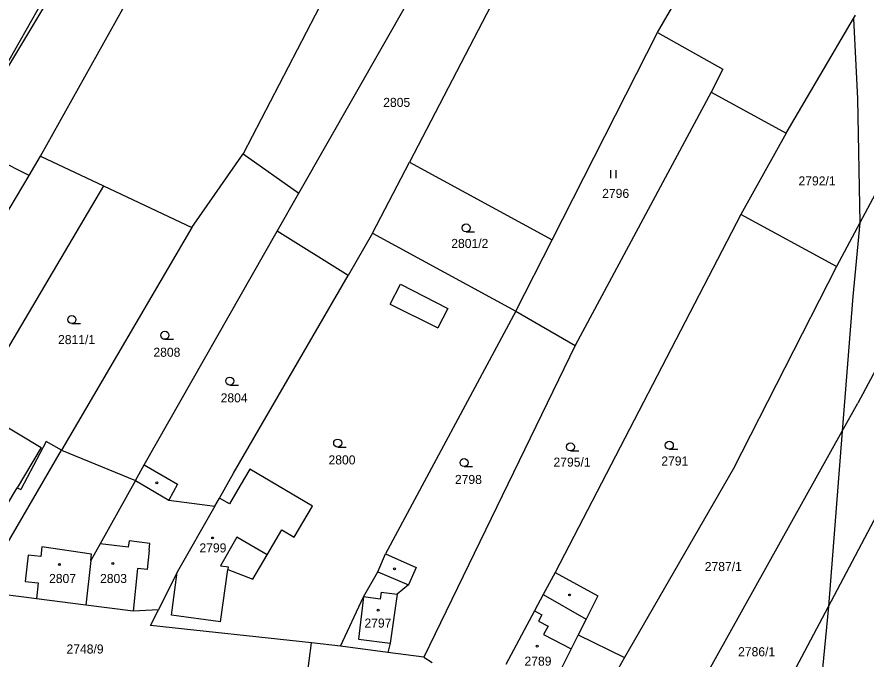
# Model space of a CAD drawing. Extents: x -755819 to -753140, y -1169796 to -1166000.
# Drawn here: x -753865.3 to -753706, y -1169016.5 to -1168896.1 of the extents above; entities that cross this region are included whole.
import ezdxf

# ---------------------------------------------------------------- set-up
doc = ezdxf.new("R2010")
doc.units = 0
for name, color, linetype in [('Vrstva 1', 7, 'Continuous'), ('Vrstva 18', 7, 'Continuous'), ('Vrstva 19', 7, 'Continuous'), ('Vrstva 25', 7, 'Continuous'), ('Vrstva 4', 7, 'Continuous'), ('Vrstva 6', 7, 'Continuous')]:
    doc.layers.add(name, color=color, linetype=linetype)

msp = doc.modelspace()

# ---------------------------------------------------------------- linework, layer by layer
at = {"layer": 'Vrstva 1'}
for p, q in [((-753776.72, -1168832.59), (-753822.86, -1168921.71)), ((-753860.84, -1168922.15), (-753819.74, -1168848.57)), ((-753745.13, -1168898.97), (-753723.98, -1168862.19)), ((-753765.92, -1168873.82), (-753791.66, -1168923.33)), ((-753812.4, -1168929.1), (-753791.66, -1168892.68)), ((-753859.75, -1168893.38), (-753875.49, -1168919.49)), ((-753708.4, -1168896.39), (-753708.03, -1168895.76)), ((-753721.02, -1168917.88), (-753708.4, -1168896.39)), ((-753708.4, -1168896.39), (-753707.61, -1168911.45)), ((-753764.9, -1168937.85), (-753745.13, -1168898.97)), ((-753745.13, -1168898.97), (-753732.89, -1168905.86)), ((-753732.89, -1168905.86), (-753735.09, -1168910.19)), ((-753735.09, -1168910.19), (-753760.61, -1168957.65)), ((-753735.09, -1168910.19), (-753721.02, -1168917.88)), ((-753707.61, -1168911.45), (-753707.21, -1168934.67)), ((-753721.02, -1168917.88), (-753729.53, -1168933.1)), ((-753863, -1168925.78), (-753875.49, -1168919.49)), ((-753863, -1168925.78), (-753860.84, -1168922.15)), ((-753860.84, -1168922.15), (-753849.08, -1168927.71)), ((-753832.5, -1168935.54), (-753822.86, -1168921.71)), ((-753822.86, -1168921.71), (-753812.4, -1168929.1)), ((-753798.58, -1168936.64), (-753791.66, -1168923.33)), ((-753791.66, -1168923.33), (-753764.9, -1168937.85)), ((-753684.02, -1168924.11), (-753707.57, -1168968.51)), ((-753908.16, -1169001.74), (-753863, -1168925.78)), ((-753849.08, -1168927.71), (-753893.24, -1169002.57)), ((-753849.08, -1168927.71), (-753832.5, -1168935.54)), ((-753702.9, -1168926.61), (-753707.21, -1168934.67)), ((-753816.46, -1168936.24), (-753812.4, -1168929.1)), ((-753713.1, -1169006.62), (-753671.62, -1168928.26)), ((-753729.53, -1168933.1), (-753764.36, -1169000.22)), ((-753711.59, -1168942.84), (-753729.53, -1168933.1)), ((-753832.5, -1168935.54), (-753856.95, -1168977.33)), ((-753707.21, -1168934.67), (-753711.59, -1168942.84)), ((-753707.21, -1168934.67), (-753708.52, -1168948.5)), ((-753841.4, -1168980.06), (-753816.46, -1168936.24)), ((-753803.16, -1168944.53), (-753816.46, -1168936.24)), ((-753798.58, -1168936.64), (-753803.16, -1168944.53)), ((-753798.58, -1168936.64), (-753771.7, -1168951.23)), ((-753771.7, -1168951.23), (-753764.9, -1168937.85)), ((-753711.59, -1168942.84), (-753730.93, -1168980.89)), ((-753824.65, -1168981.62), (-753803.16, -1168944.53)), ((-753708.52, -1168948.5), (-753710.51, -1168973.77)), ((-753771.7, -1168951.23), (-753796.14, -1168996.72)), ((-753771.7, -1168951.23), (-753760.61, -1168957.65)), ((-753760.61, -1168957.65), (-753788.98, -1169016.12)), ((-753710.51, -1168973.77), (-753707.57, -1168968.51)), ((-753870.59, -1168970.91), (-753860.74, -1168976.78)), ((-753743.31, -1169032.56), (-753710.51, -1168973.77)), ((-753710.51, -1168973.77), (-753713.1, -1169006.62)), ((-753859.78, -1168975.69), (-753864.57, -1168984.66)), ((-753856.95, -1168977.33), (-753859.78, -1168975.69)), ((-753867.49, -1168995.5), (-753856.95, -1168977.33)), ((-753860.74, -1168976.78), (-753865.24, -1168984.37)), ((-753856.95, -1168977.33), (-753843.08, -1168983.01)), ((-753843.08, -1168983.01), (-753841.4, -1168980.06)), ((-753841.4, -1168980.06), (-753835.18, -1168983.66)), ((-753827.3, -1168986.28), (-753824.65, -1168981.62)), ((-753821.62, -1168980.87), (-753823.43, -1168983.94)), ((-753809.86, -1168987.78), (-753821.62, -1168980.87)), ((-753730.93, -1168980.89), (-753751.33, -1169016.18)), ((-753843.08, -1168983.01), (-753849.68, -1168994.84)), ((-753835.18, -1168983.66), (-753836.78, -1168986.68)), ((-753865.24, -1168984.37), (-753864.57, -1168984.66)), ((-753823.43, -1168983.94), (-753825.4, -1168987.38)), ((-753836.78, -1168986.68), (-753828.16, -1168987.79)), ((-753828.16, -1168987.79), (-753827.3, -1168986.28)), ((-753825.4, -1168987.38), (-753827.3, -1168986.28)), ((-753828.16, -1168987.79), (-753835.24, -1169000.21)), ((-753813.3, -1168993.62), (-753809.86, -1168987.78)), ((-753818.34, -1168996.91), (-753815.63, -1168992.25)), ((-753815.63, -1168992.25), (-753813.3, -1168993.62)), ((-753849.68, -1168994.84), (-753851.42, -1168997.97)), ((-753851.42, -1168997.97), (-753852.36, -1169006.37)), ((-753821.05, -1169001.52), (-753818.34, -1168996.91)), ((-753797.6, -1169000.1), (-753796.14, -1168996.72)), ((-753796.14, -1168996.72), (-753790.41, -1168999.28)), ((-753827.1, -1169009.48), (-753825.75, -1168999.67)), ((-753825.75, -1168999.67), (-753821.05, -1169001.52)), ((-753790.41, -1168999.28), (-753791.87, -1169002.56)), ((-753835.24, -1169000.21), (-753838.76, -1169007.23)), ((-753836.28, -1169008.26), (-753835.24, -1169000.21)), ((-753800.29, -1169004.83), (-753797.6, -1169000.1)), ((-753764.36, -1169000.22), (-753766.57, -1169004.35)), ((-753764.36, -1169000.22), (-753756.31, -1169004.64)), ((-753791.87, -1169002.56), (-753793.98, -1169004.32)), ((-753864.02, -1169004.86), (-753872.23, -1169003.8)), ((-753793.98, -1169004.32), (-753795.28, -1169013.5)), ((-753766.57, -1169004.35), (-753768.22, -1169007.42)), ((-753861.64, -1169005.17), (-753864.02, -1169004.86)), ((-753852.36, -1169006.37), (-753861.64, -1169005.17)), ((-753804.59, -1169014.03), (-753800.29, -1169004.83)), ((-753756.31, -1169004.64), (-753758.51, -1169008.97)), ((-753843.51, -1169007.48), (-753852.36, -1169006.37)), ((-753838.76, -1169007.23), (-753843.51, -1169007.48)), ((-753840.24, -1169010.18), (-753838.76, -1169007.23)), ((-753768.22, -1169007.42), (-753773.61, -1169017.48)), ((-753732.98, -1169044.16), (-753713.1, -1169006.62)), ((-753713.1, -1169006.62), (-753717.26, -1169050.5)), ((-753827.1, -1169009.48), (-753836.28, -1169008.26)), ((-753758.51, -1169008.97), (-753760, -1169011.91)), ((-753810.05, -1169013.44), (-753840.24, -1169010.18)), ((-753760, -1169011.91), (-753761.35, -1169014.59)), ((-753760, -1169011.91), (-753751.33, -1169016.18)), ((-753811.64, -1169025.68), (-753810.05, -1169013.44)), ((-753804.59, -1169014.03), (-753810.05, -1169013.44)), ((-753795.28, -1169013.5), (-753795.7, -1169015.22)), ((-753795.7, -1169015.22), (-753804.59, -1169014.03)), ((-753788.98, -1169016.12), (-753795.7, -1169015.22)), ((-753761.35, -1169014.59), (-753764.74, -1169021.36)), ((-753788.98, -1169016.12), (-753787.44, -1169017.11)), ((-753751.33, -1169016.18), (-753758.36, -1169028.42))]:
    msp.add_line(p, q, dxfattribs=at)
at = {"layer": 'Vrstva 25'}
for p, q in [((-753753.87, -1168926.33), (-753753.87, -1168924.83)), ((-753752.87, -1168926.33), (-753752.87, -1168924.83)), ((-753781.04, -1168936.37), (-753779.44, -1168936.37)), ((-753854.99, -1168953.57), (-753853.39, -1168953.57)), ((-753837.54, -1168956.52), (-753835.94, -1168956.52)), ((-753825.36, -1168965.09), (-753823.76, -1168965.09)), ((-753805.13, -1168976.72), (-753803.53, -1168976.72)), ((-753742.93, -1168977.13), (-753741.33, -1168977.13)), ((-753761.47, -1168977.44), (-753759.87, -1168977.44)), ((-753781.43, -1168980.39), (-753779.83, -1168980.39))]:
    msp.add_line(p, q, dxfattribs=at)
for centre, radius in [((-753781.04, -1168935.62), 0.75), ((-753854.99, -1168952.82), 0.75), ((-753837.54, -1168955.77), 0.75), ((-753825.36, -1168964.34), 0.75), ((-753805.13, -1168975.97), 0.75), ((-753742.93, -1168976.38), 0.75), ((-753761.47, -1168976.69), 0.75), ((-753781.43, -1168979.64), 0.75), ((-753839.06, -1168983.45), 0.175), ((-753828.58, -1168993.77), 0.175), ((-753857.33, -1168998.75), 0.175), ((-753847.32, -1168998.54), 0.175), ((-753794.47, -1168999.56), 0.175), ((-753761.63, -1169004.46), 0.175), ((-753797.52, -1169007.31), 0.175), ((-753767.72, -1169014.05), 0.175)]:
    msp.add_circle(centre, radius, dxfattribs=at)
at = {"layer": 'Vrstva 4'}
for p, q in [((-753795.3, -1168949.92), (-753793.35, -1168946.15)), ((-753793.35, -1168946.15), (-753784.49, -1168950.71)), ((-753795.3, -1168949.92), (-753786.37, -1168954.36)), ((-753784.49, -1168950.71), (-753786.37, -1168954.36)), ((-753843.08, -1168983.01), (-753836.78, -1168986.68)), ((-753867.34, -1168987.91), (-753865.24, -1168984.37)), ((-753844.42, -1168995.52), (-753849.68, -1168994.84)), ((-753844.26, -1168994.32), (-753844.42, -1168995.52)), ((-753840.36, -1168994.82), (-753844.26, -1168994.32)), ((-753840.51, -1168996.02), (-753840.36, -1168994.82)), ((-753824.02, -1168993.63), (-753827.13, -1168998.98)), ((-753818.34, -1168996.91), (-753824.02, -1168993.63)), ((-753860.59, -1168995.42), (-753860.82, -1168997.25)), ((-753851.29, -1168996.82), (-753860.59, -1168995.42)), ((-753840.8, -1168999.7), (-753840.41, -1168996.03)), ((-753840.41, -1168996.03), (-753840.51, -1168996.02)), ((-753863.21, -1168997), (-753863.72, -1169001.96)), ((-753860.82, -1168997.25), (-753863.21, -1168997)), ((-753851.42, -1168997.97), (-753851.29, -1168996.82)), ((-753842.66, -1168999.51), (-753843.51, -1169007.48)), ((-753840.8, -1168999.7), (-753842.66, -1168999.51)), ((-753827.13, -1168998.98), (-753826.05, -1168999.11)), ((-753826.05, -1168999.11), (-753825.68, -1168999.17)), ((-753825.68, -1168999.17), (-753825.75, -1168999.67)), ((-753797.6, -1169000.1), (-753791.87, -1169002.56)), ((-753863.72, -1169001.96), (-753861.33, -1169002.2)), ((-753861.33, -1169002.2), (-753861.64, -1169005.17)), ((-753796.96, -1169003.91), (-753797.14, -1169005.26)), ((-753796.96, -1169003.91), (-753793.98, -1169004.32)), ((-753766.57, -1169004.35), (-753758.51, -1169008.97)), ((-753800.29, -1169004.83), (-753801.21, -1169012.75)), ((-753797.14, -1169005.26), (-753800.29, -1169004.83)), ((-753768.22, -1169007.42), (-753766.83, -1169008.16)), ((-753766.83, -1169008.16), (-753767.45, -1169009.35)), ((-753767.45, -1169009.35), (-753765.66, -1169010.29)), ((-753765.66, -1169010.29), (-753766.5, -1169011.87)), ((-753766.5, -1169011.87), (-753761.35, -1169014.59)), ((-753801.21, -1169012.75), (-753795.28, -1169013.5))]:
    msp.add_line(p, q, dxfattribs=at)
at = {"layer": 'Vrstva 6'}
msp.add_line((-753860.44, -1168892.98), (-753875.49, -1168919.49), dxfattribs=at)

# ---------------------------------------------------------------- texts
at = {"layer": 'Vrstva 18'}
for s, p in [('2805', (-753796.59, -1168912.94)), ('2792/1', (-753718.7, -1168927.66)), ('2796', (-753755.52, -1168930.01)), ('2801/2', (-753783.83, -1168939.39)), ('2811/1', (-753857.58, -1168957.42)), ('2808', (-753839.69, -1168959.79)), ('2804', (-753827.08, -1168968.35)), ('2800', (-753806.85, -1168979.98)), ('2795/1', (-753764.65, -1168980.4)), ('2791', (-753744.43, -1168980.19)), ('2798', (-753783.14, -1168983.65)), ('2787/1', (-753736.28, -1168999.98)), ('2748/9', (-753855.99, -1169015.44)), ('2786/1', (-753730.03, -1169015.95))]:
    msp.add_text(s, height=1.7, dxfattribs=at).set_placement(p)
at = {"layer": 'Vrstva 19'}
for s, p in [('2799', (-753831.06, -1168996.48)), ('2807', (-753859.26, -1169002.22)), ('2803', (-753849.7, -1169002.22)), ('2797', (-753800.11, -1169010.58)), ('2789', (-753770.09, -1169017.72))]:
    msp.add_text(s, height=1.7, dxfattribs=at).set_placement(p)

doc.saveas('drawing.dxf')
